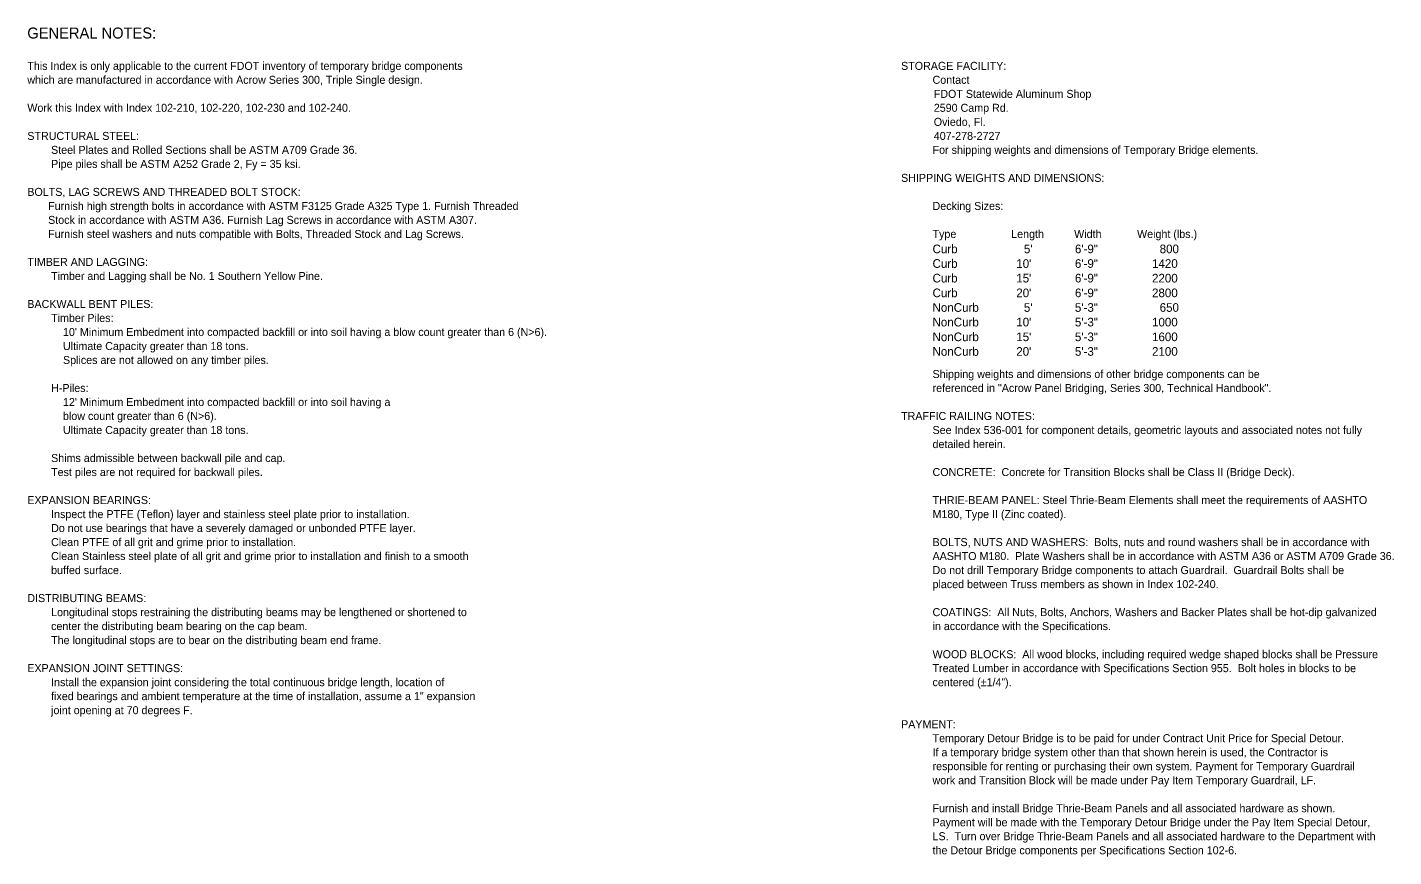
# Model space of a CAD drawing. Extents: x 1.2 to 13.4, y 1.1 to 8.5.
import ezdxf

# ---------------------------------------------------------------- set-up
doc = ezdxf.new("R2010")
doc.units = 0
doc.layers.add('TextStructures', color=7, linetype='Continuous')

msp = doc.modelspace()

# ---------------------------------------------------------------- texts
at = {"layer": 'TextStructures'}
for s, height, p in [('GENERAL NOTES:', 0.09768, (1.208, 8.372)), ('This Index is only applicable to the current FDOT inventory of temporary bridge components', 0.0712, (1.208, 8.093)), ('STORAGE FACILITY:', 0.0712, (8.983, 8.093)), ('which are manufactured in accordance with Acrow Series 300, Triple Single design.', 0.0712, (1.208, 7.969)), ('Contact ', 0.0712, (9.263, 7.969)), ('           FDOT Statewide Aluminum Shop', 0.0712, (8.983, 7.844)), ('Work this Index with Index 102-210, 102-220, 102-230 and 102-240.', 0.0712, (1.208, 7.72)), ('           2590 Camp Rd.', 0.0712, (8.983, 7.72)), ('           Oviedo, Fl.', 0.0712, (8.983, 7.595)), ('STRUCTURAL STEEL:', 0.0712, (1.208, 7.47)), ('           407-278-2727', 0.0712, (8.983, 7.47)), ('        Steel Plates and Rolled Sections shall be ASTM A709 Grade 36. ', 0.0712, (1.208, 7.346)), ('For shipping weights and dimensions of Temporary Bridge elements.', 0.0712, (9.263, 7.346)), ('        Pipe piles shall be ASTM A252 Grade 2, Fy = 35 ksi.', 0.0712, (1.208, 7.221)), ('SHIPPING WEIGHTS AND DIMENSIONS:', 0.0712, (8.983, 7.097)), ('BOLTS, LAG SCREWS AND THREADED BOLT STOCK:', 0.0712, (1.208, 6.972)), ('       Furnish high strength bolts in accordance with ASTM F3125 Grade A325 Type 1. Furnish Threaded ', 0.071196, (1.208, 6.847)), ('Decking Sizes:', 0.0712, (9.263, 6.847)), ('       Stock in accordance with ASTM A36. Furnish Lag Screws in accordance with ASTM A307. ', 0.0712, (1.208, 6.723)), ('       Furnish steel washers and nuts compatible with Bolts, Threaded Stock and Lag Screws.', 0.0712, (1.208, 6.598)), ('Type', 0.0712, (9.263, 6.598)), ('Length', 0.0712, (9.963, 6.598)), ('Width', 0.0712, (10.523, 6.598)), ('Weight (lbs.)', 0.0712, (11.083, 6.598)), ('Curb', 0.0769, (9.263, 6.462)), ("5'", 0.0769, (10.076, 6.462)), ('6\'-9"', 0.0769, (10.53, 6.462)), ('800', 0.0769, (11.284, 6.462)), ('TIMBER AND LAGGING:', 0.0712, (1.208, 6.349)), ('Curb', 0.0769, (9.263, 6.332)), ("10'", 0.0769, (10.008, 6.332)), ('6\'-9"', 0.0769, (10.53, 6.332)), ('1420', 0.0769, (11.216, 6.332)), ('        Timber and Lagging shall be No. 1 Southern Yellow Pine.', 0.0712, (1.208, 6.224)), ('Curb', 0.0769, (9.263, 6.202)), ("15'", 0.0769, (10.008, 6.202)), ('6\'-9"', 0.0769, (10.53, 6.202)), ('2200', 0.0769, (11.216, 6.202)), ('Curb', 0.0769, (9.263, 6.071)), ("20'", 0.0769, (10.008, 6.071)), ('6\'-9"', 0.0769, (10.53, 6.071)), ('2800', 0.0769, (11.216, 6.071)), ('BACKWALL BENT PILES:', 0.0712, (1.208, 5.975)), ('NonCurb', 0.0769, (9.263, 5.941)), ("5'", 0.0769, (10.076, 5.941)), ('5\'-3"', 0.0769, (10.53, 5.941)), ('650', 0.0769, (11.284, 5.941)), ('        Timber Piles: ', 0.0712, (1.208, 5.851)), ('NonCurb', 0.0769, (9.263, 5.811)), ("10'", 0.0769, (10.008, 5.811)), ('5\'-3"', 0.0769, (10.53, 5.811)), ('1000', 0.0769, (11.216, 5.811)), ("            10' Minimum Embedment into compacted backfill or into soil having a blow count greater than 6 (N>6).", 0.071196, (1.208, 5.726)), ('NonCurb', 0.0769, (9.263, 5.68)), ("15'", 0.0769, (10.008, 5.68)), ('5\'-3"', 0.0769, (10.53, 5.68)), ('1600', 0.0769, (11.216, 5.68)), ('            Ultimate Capacity greater than 18 tons.', 0.0712, (1.208, 5.601)), ('NonCurb', 0.0769, (9.263, 5.55)), ("20'", 0.0769, (10.008, 5.55)), ('5\'-3"', 0.0769, (10.53, 5.55)), ('2100', 0.0769, (11.216, 5.55)), ('            Splices are not allowed on any timber piles.', 0.0712, (1.208, 5.477)), ('Shipping weights and dimensions of other bridge components can be ', 0.0712, (9.263, 5.352)), ('        H-Piles: ', 0.0712, (1.208, 5.228)), ('referenced in "Acrow Panel Bridging, Series 300, Technical Handbook".     ', 0.0712, (9.263, 5.228)), ("            12' Minimum Embedment into compacted backfill or into soil having a ", 0.0712, (1.208, 5.103)), ('            blow count greater than 6 (N>6).', 0.0712, (1.208, 4.979)), ('TRAFFIC RAILING NOTES:', 0.0712, (8.983, 4.979)), ('            Ultimate Capacity greater than 18 tons.', 0.0712, (1.208, 4.854)), ('See Index 536-001 for component details, geometric layouts and associated notes not fully ', 0.0712, (9.263, 4.854)), ('detailed herein.', 0.0712, (9.263, 4.729)), ('        Shims admissible between backwall pile and cap.', 0.0712, (1.208, 4.605)), ('        Test piles are not required for backwall piles.', 0.0712, (1.208, 4.48)), ('CONCRETE:  Concrete for Transition Blocks shall be Class II (Bridge Deck).', 0.0712, (9.263, 4.48)), ('EXPANSION BEARINGS:', 0.0712, (1.208, 4.231)), ('THRIE-BEAM PANEL: Steel Thrie-Beam Elements shall meet the requirements of AASHTO ', 0.0712, (9.263, 4.231)), ('        Inspect the PTFE (Teflon) layer and stainless steel plate prior to installation.', 0.0712, (1.208, 4.106)), ('M180, Type II (Zinc coated).', 0.0712, (9.263, 4.106)), ('        Do not use bearings that have a severely damaged or unbonded PTFE layer.', 0.0712, (1.208, 3.982)), ('        Clean PTFE of all grit and grime prior to installation.', 0.0712, (1.208, 3.857)), ('BOLTS, NUTS AND WASHERS:  Bolts, nuts and round washers shall be in accordance with ', 0.0712, (9.263, 3.857)), ('        Clean Stainless steel plate of all grit and grime prior to installation and finish to a smooth ', 0.071196, (1.208, 3.733)), ('AASHTO M180.  Plate Washers shall be in accordance with ASTM A36 or ASTM A709 Grade 36.  ', 0.0712, (9.263, 3.733)), ('        buffed surface.', 0.0712, (1.208, 3.608)), ('Do not drill Temporary Bridge components to attach Guardrail.  Guardrail Bolts shall be ', 0.0712, (9.263, 3.608)), ('placed between Truss members as shown in Index 102-240.', 0.0712, (9.263, 3.483)), ('DISTRIBUTING BEAMS:', 0.0712, (1.208, 3.359)), ('        Longitudinal stops restraining the distributing beams may be lengthened or shortened to ', 0.0712, (1.208, 3.234)), ('COATINGS:  All Nuts, Bolts, Anchors, Washers and Backer Plates shall be hot-dip galvanized ', 0.0712, (9.263, 3.234)), ('        center the distributing beam bearing on the cap beam.', 0.0712, (1.208, 3.11)), ('in accordance with the Specifications.', 0.0712, (9.263, 3.11)), ('        The longitudinal stops are to bear on the distributing beam end frame.', 0.0712, (1.208, 2.985)), ('WOOD BLOCKS:  All wood blocks, including required wedge shaped blocks shall be Pressure ', 0.0712, (9.263, 2.86)), ('EXPANSION JOINT SETTINGS:', 0.0712, (1.208, 2.736)), ('Treated Lumber in accordance with Specifications Section 955.  Bolt holes in blocks to be ', 0.0712, (9.263, 2.736)), ('        Install the expansion joint considering the total continuous bridge length, location of ', 0.0712, (1.208, 2.611)), ('centered (±1/4”).', 0.0712, (9.263, 2.611)), ('        fixed bearings and ambient temperature at the time of installation, assume a 1" expansion ', 0.0712, (1.208, 2.487)), ('        joint opening at 70 degrees F. ', 0.0712, (1.208, 2.362)), ('PAYMENT:', 0.0712, (8.983, 2.237)), ('Temporary Detour Bridge is to be paid for under Contract Unit Price for Special Detour.', 0.0712, (9.263, 2.113)), ('If a temporary bridge system other than that shown herein is used, the Contractor is ', 0.0712, (9.263, 1.988)), ('responsible for renting or purchasing their own system. Payment for Temporary Guardrail ', 0.0712, (9.263, 1.864)), ('work and Transition Block will be made under Pay Item Temporary Guardrail, LF.', 0.0712, (9.263, 1.739)), ('Furnish and install Bridge Thrie-Beam Panels and all associated hardware as shown.  ', 0.0712, (9.263, 1.49)), ('Payment will be made with the Temporary Detour Bridge under the Pay Item Special Detour, ', 0.0712, (9.263, 1.365)), ('LS.  Turn over Bridge Thrie-Beam Panels and all associated hardware to the Department with ', 0.0712, (9.263, 1.241)), ('the Detour Bridge components per Specifications Section 102-6.', 0.0712, (9.263, 1.116))]:
    msp.add_text(s, height=height, dxfattribs=at).set_placement(p)

doc.saveas('drawing.dxf')
